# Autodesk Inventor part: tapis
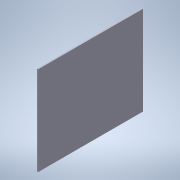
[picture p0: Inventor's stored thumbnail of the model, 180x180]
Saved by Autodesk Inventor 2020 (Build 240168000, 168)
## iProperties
Created: 2021-10
Part Number: tapis
Material: Générique
Document SubType Name: Modeling
Designer: bruno
Density: 1 g/cm^3
Appearance: Blanc froid
Author: bruno
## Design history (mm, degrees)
sketch "Esquisse1"
  geometry: L1 (0, 0)-(305.633, 0); L2 (305.633, 0)-(305.633, -800); L3 (305.633, -800)-(0, -800); L4 (0, -800)-(0, 0)
  constraints: 8 end point, 2 parallel, 1 horizontal, 1 perpendicular
  dimensions: "d2" = 800 distance of L1.end L2.end
extrude "Extrusion1" new body sketch "Esquisse1" distance "d0" = 10; taper "d1" = 0 deg
node "Solide1"
